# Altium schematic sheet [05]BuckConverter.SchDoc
size A4; SheetNumber: 4; SheetTotal: 5
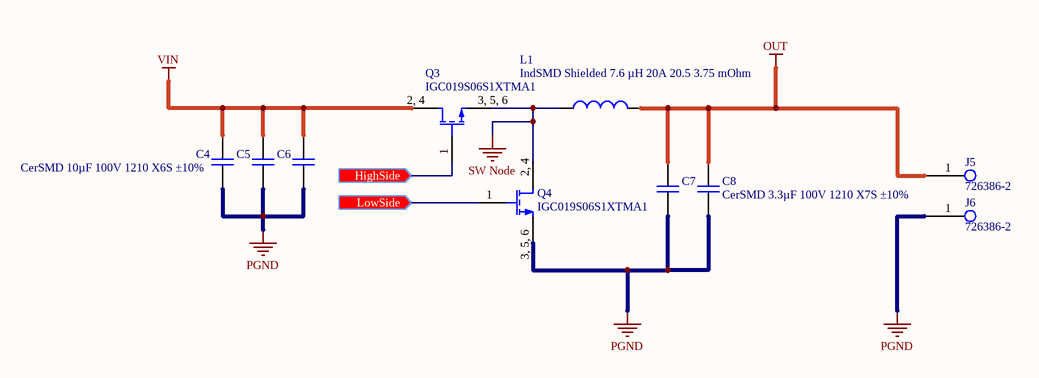
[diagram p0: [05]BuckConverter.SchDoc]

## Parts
C4  CerSMD 10µF 100V 1210 X6S ±10%  [CAPC3216X18N]
C5  CerSMD 10µF 100V 1210 X6S ±10%  [CAPC3216X18N]  (value not drawn)
C6  CerSMD 10µF 100V 1210 X6S ±10%  [CAPC3216X18N]  (value not drawn)
C7  CerSMD 3.3µF 100V 1210 X7S ±10%  [CAPC3225X28N]  (value not drawn)
C8  CerSMD 3.3µF 100V 1210 X7S ±10%  [CAPC3225X28N]
J5  726386-2  [1844210]
J6  726386-2  [1844210]
L1  IndSMD Shielded 7.6 µH 20A 20.5 3.75 mOhm  [7443557760]
Q3  IGC019S06S1XTMA1  [IGC019S06S1XTMA1]
Q4  IGC019S06S1XTMA1  [IGC019S06S1XTMA1]

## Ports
HighSide (in, see [03]GateDriver[3B]), LowSide (in, see [03]GateDriver[3C])

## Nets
OUT: C7.1 C8.1 J5.1 L1.2
PGND: C4.2 C5.2 C6.2 C7.2 C8.2 J6.1 Q4.3,_5,_6(S)
SW Node: L1.1 Q3.3,_5,_6(S) Q4.2,_4(D)
VIN: C4.1 C5.1 C6.1 Q3.2,_4(D)
HighSide: Q3.1(G) ; port HighSide
LowSide: Q4.1(G) ; port LowSide

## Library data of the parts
C4-C6 = CMP-000078-1: Ceramic Capacitor SMD 10µF 100V 1210 X6S ±10%; Manufacturer: TDK Corporation; Manufacturer Number: C3216X6S2A106K160AC; Temperature Coefficient: X7R; Voltage: 16V
C7 C8 = CMP-00010-1: Ceramic Capacitor SMD 3.3µF 100V 1210 X7S ±10%; Manufacturer: Samsung Electro-Mechanics; Manufacturer Number: C3225X7S2A335K200AB; Voltage: 16V; Temperature Coefficient: X7R
J5 J6 = CMP-00026-1
L1 = CMP-00011-1: Inductor SMD Shielded 7.6 µH 20A 20.5 3.75 mOhm
Q3 Q4 = CMP-00009-5: GaNFET N-Ch - 60V - 27A (Ta), 99A (Tc); Manufacturer: Infineon Technologies; Vgs(max): ±6.5V; Rdson: 1.9mOhm; Vgs(th): 2.9V; Drive Voltage: 5V; FET Type: N-Channel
